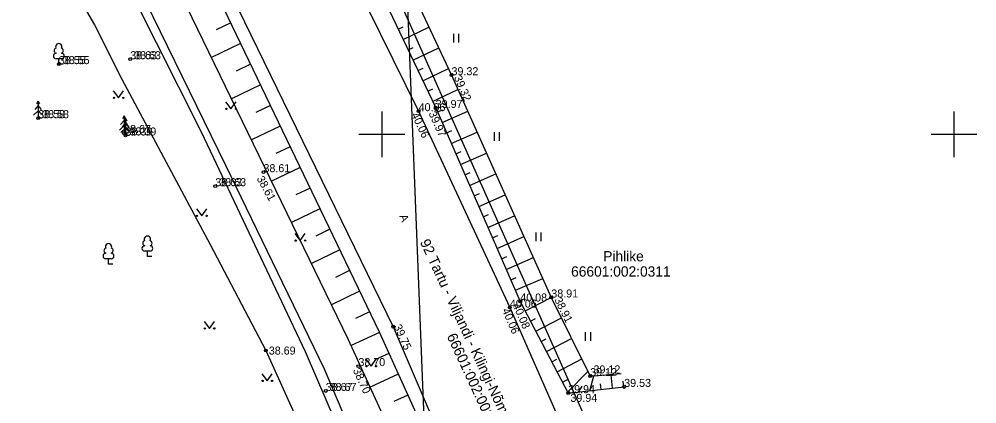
# Model space of a CAD drawing. Extents: x 627548 to 628052, y 6467984 to 6468802.
# Drawn here: x 627818.3 to 627902, y 6468376.5 to 6468410.1 of the extents above; entities that cross this region are included whole.
import ezdxf

# ---------------------------------------------------------------- set-up
doc = ezdxf.new("R2010")
doc.units = 0
for name, color, linetype in [('HALJASTUS', 7, 'Continuous'), ('KORGUS-EH2000', 7, 'Continuous'), ('MOOTKORG-EH2000', 7, 'Continuous'), ('MOOTMPUNKT', 7, 'Continuous'), ('PIIR', 7, 'Continuous'), ('PUU', 7, 'Continuous'), ('RELJEEF', 7, 'Continuous'), ('SITRASS', 7, 'Continuous'), ('TEE', 7, 'Continuous'), ('VORK', 7, 'Continuous')]:
    doc.layers.add(name, color=color, linetype=linetype)

msp = doc.modelspace()

# ---------------------------------------------------------------- linework, layer by layer
at = {"layer": 'HALJASTUS'}
for p, q in [((627856.255, 6468408.773), (627856.255, 6468408.012)), ((627856.71, 6468408.773), (627856.71, 6468408.012)), ((627826.529, 6468403.791), (627826.992, 6468403.184)), ((627826.992, 6468403.184), (627827.438, 6468403.791)), ((627836.354, 6468402.828), (627836.817, 6468402.222)), ((627836.817, 6468402.222), (627837.263, 6468402.828)), ((627859.816, 6468400.181), (627859.816, 6468399.42)), ((627860.271, 6468400.181), (627860.271, 6468399.42)), ((627833.798, 6468393.48), (627834.261, 6468392.874)), ((627834.261, 6468392.874), (627834.707, 6468393.48)), ((627842.41, 6468391.319), (627842.874, 6468390.712)), ((627842.874, 6468390.712), (627843.319, 6468391.319)), ((627863.455, 6468391.419), (627863.455, 6468390.658)), ((627863.91, 6468391.419), (627863.91, 6468390.658)), ((627834.472, 6468383.652), (627834.935, 6468383.046)), ((627834.935, 6468383.046), (627835.381, 6468383.652)), ((627867.777, 6468382.713), (627867.777, 6468381.952)), ((627868.232, 6468382.713), (627868.232, 6468381.952)), ((627848.601, 6468380.345), (627849.065, 6468379.738)), ((627849.065, 6468379.738), (627849.51, 6468380.345)), ((627839.519, 6468379.067), (627839.983, 6468378.46)), ((627839.983, 6468378.46), (627840.428, 6468379.067))]:
    msp.add_line(p, q, dxfattribs=at)
for centre in [(627826.591, 6468403.184), (627827.42, 6468403.184), (627836.416, 6468402.222), (627837.245, 6468402.222), (627833.86, 6468392.874), (627834.689, 6468392.874), (627842.473, 6468390.712), (627843.302, 6468390.712), (627834.534, 6468383.046), (627835.363, 6468383.046), (627848.664, 6468379.738), (627849.493, 6468379.738), (627839.582, 6468378.46), (627840.41, 6468378.46)]:
    msp.add_circle(centre, 0.055, dxfattribs=at)
at = {"layer": 'KORGUS-EH2000'}
for centre in [(627850.99, 6468383.197), (627839.865, 6468381.11)]:
    msp.add_circle(centre, 0.125, dxfattribs=at)
at = {"layer": 'MOOTMPUNKT'}
for centre in [(627821.775, 6468406.124), (627828.009, 6468406.553), (627856.095, 6468405.157), (627853.219, 6468402.014), (627854.711, 6468402.298), (627819.972, 6468401.404), (627827.479, 6468400.109), (627827.604, 6468399.895), (627839.659, 6468396.688), (627835.45, 6468395.464), (627862.101, 6468385.395), (627864.813, 6468385.745), (627861.194, 6468384.862), (627847.957, 6468379.753), (627868.21, 6468378.879), (627845.098, 6468377.582), (627871.184, 6468377.936), (627866.289, 6468377.389)]:
    msp.add_circle(centre, 0.125, dxfattribs=at)
at = {"layer": 'PIIR'}
for p, q in [((627893.5, 6468317.49), (627836.88, 6468444.6)), ((627826.02, 6468416.53), (627834.21, 6468400.21)), ((627834.21, 6468400.21), (627843.3, 6468381.02)), ((627843.3, 6468381.02), (627850.92, 6468363.47))]:
    msp.add_line(p, q, dxfattribs=at)
at = {"layer": 'PUU'}
for p, q in [((627822.015, 6468406.599), (627821.535, 6468406.599)), ((627821.775, 6468406.124), (627821.775, 6468406.599)), ((627822.155, 6468406.124), (627821.775, 6468406.124)), ((627819.972, 6468402.904), (627819.822, 6468402.654)), ((627820.122, 6468402.654), (627819.972, 6468402.904)), ((627819.972, 6468402.904), (627819.972, 6468401.404)), ((627819.972, 6468402.054), (627819.572, 6468401.654)), ((627819.972, 6468402.504), (627819.672, 6468402.154)), ((627820.272, 6468402.154), (627819.972, 6468402.504)), ((627820.372, 6468401.654), (627819.972, 6468402.054)), ((627820.332, 6468401.404), (627819.972, 6468401.404)), ((627827.479, 6468401.209), (627827.179, 6468400.859)), ((627827.604, 6468400.995), (627827.304, 6468400.645)), ((627827.479, 6468401.609), (627827.329, 6468401.359)), ((627827.604, 6468401.395), (627827.454, 6468401.145)), ((627827.629, 6468401.359), (627827.479, 6468401.609)), ((627827.479, 6468401.609), (627827.479, 6468400.109)), ((627827.779, 6468400.859), (627827.479, 6468401.209)), ((627827.754, 6468401.145), (627827.604, 6468401.395)), ((627827.604, 6468401.395), (627827.604, 6468399.895)), ((627827.904, 6468400.645), (627827.604, 6468400.995)), ((627827.479, 6468400.759), (627827.079, 6468400.359)), ((627827.604, 6468400.545), (627827.204, 6468400.145)), ((627827.879, 6468400.359), (627827.479, 6468400.759)), ((627828.004, 6468400.145), (627827.604, 6468400.545)), ((627827.839, 6468400.109), (627827.479, 6468400.109)), ((627827.964, 6468399.895), (627827.604, 6468399.895)), ((627829.759, 6468389.792), (627829.279, 6468389.792)), ((627829.519, 6468389.317), (627829.519, 6468389.792)), ((627829.899, 6468389.317), (627829.519, 6468389.317)), ((627826.362, 6468389.129), (627825.882, 6468389.129)), ((627826.122, 6468388.654), (627826.122, 6468389.129)), ((627826.502, 6468388.654), (627826.122, 6468388.654))]:
    msp.add_line(p, q, dxfattribs=at)
for centre, radius, start, end in [((627821.775, 6468407.644), 0.277, 332.5799, 207.4201), ((627821.538, 6468406.836), 0.238, 90.0016, 269.3953), ((627821.605, 6468407.297), 0.233, 109.02174, 253.14154), ((627821.945, 6468407.297), 0.233, 286.85082, 70.98591), ((627822.012, 6468406.836), 0.238, 270.6047, 89.9984), ((627829.519, 6468390.837), 0.277, 332.5799, 207.4201), ((627826.122, 6468390.174), 0.277, 332.5799, 207.4201), ((627829.282, 6468390.03), 0.238, 90.0016, 269.3953), ((627829.349, 6468390.49), 0.233, 109.02174, 253.14154), ((627829.689, 6468390.49), 0.233, 286.85082, 70.98591), ((627829.757, 6468390.03), 0.238, 270.6047, 89.9984), ((627825.884, 6468389.367), 0.238, 90.0016, 269.3953), ((627825.952, 6468389.827), 0.233, 109.02174, 253.14154), ((627826.292, 6468389.827), 0.233, 286.85082, 70.98591), ((627826.359, 6468389.367), 0.238, 270.6047, 89.9984)]:
    msp.add_arc(centre, radius, start, end, dxfattribs=at)
at = {"layer": 'RELJEEF'}
for p, q in [((627836.798, 6468409.725), (627835.522, 6468409.112)), ((627851.43, 6468409.171), (627851.881, 6468409.387)), ((627851.861, 6468408.269), (627854.126, 6468409.35)), ((627837.665, 6468407.923), (627835.12, 6468406.7)), ((627852.291, 6468407.366), (627852.743, 6468407.582)), ((627852.722, 6468406.464), (627854.976, 6468407.54)), ((627838.531, 6468406.12), (627837.262, 6468405.51)), ((627853.153, 6468405.561), (627853.604, 6468405.777)), ((627853.584, 6468404.659), (627855.826, 6468405.729)), ((627839.397, 6468404.317), (627836.868, 6468403.102)), ((627854.015, 6468403.757), (627854.466, 6468403.972)), ((627854.446, 6468402.854), (627856.655, 6468403.909)), ((627840.263, 6468402.515), (627839.002, 6468401.909)), ((627854.865, 6468401.946), (627855.323, 6468402.147)), ((627855.265, 6468401.03), (627857.508, 6468402.011)), ((627841.129, 6468400.712), (627838.616, 6468399.504)), ((627855.666, 6468400.114), (627856.124, 6468400.314)), ((627856.067, 6468399.198), (627858.327, 6468400.186)), ((627841.996, 6468398.909), (627840.743, 6468398.307)), ((627856.467, 6468398.281), (627856.925, 6468398.482)), ((627856.868, 6468397.365), (627859.147, 6468398.362)), ((627842.862, 6468397.106), (627840.363, 6468395.906)), ((627857.268, 6468396.449), (627857.726, 6468396.649)), ((627857.669, 6468395.533), (627859.966, 6468396.537)), ((627843.728, 6468395.304), (627842.483, 6468394.705)), ((627858.069, 6468394.616), (627858.528, 6468394.817)), ((627858.47, 6468393.7), (627860.786, 6468394.712)), ((627844.594, 6468393.501), (627842.111, 6468392.308)), ((627858.871, 6468392.784), (627859.329, 6468392.984)), ((627859.271, 6468391.868), (627861.605, 6468392.888)), ((627845.46, 6468391.698), (627844.223, 6468391.104)), ((627859.672, 6468390.951), (627860.13, 6468391.152)), ((627860.072, 6468390.035), (627862.425, 6468391.063)), ((627846.327, 6468389.896), (627843.859, 6468388.71)), ((627860.473, 6468389.119), (627860.931, 6468389.319)), ((627860.874, 6468388.202), (627863.244, 6468389.239)), ((627847.193, 6468388.093), (627845.963, 6468387.502)), ((627861.274, 6468387.286), (627861.732, 6468387.487)), ((627861.675, 6468386.37), (627864.063, 6468387.414)), ((627848.059, 6468386.29), (627845.606, 6468385.112)), ((627862.075, 6468385.454), (627862.533, 6468385.654)), ((627862.535, 6468384.566), (627864.808, 6468385.755)), ((627848.925, 6468384.488), (627847.703, 6468383.9)), ((627862.998, 6468383.68), (627863.441, 6468383.911)), ((627863.462, 6468382.794), (627865.695, 6468383.962)), ((627849.79, 6468382.684), (627847.317, 6468381.562)), ((627863.925, 6468381.907), (627864.368, 6468382.139)), ((627864.389, 6468381.021), (627866.582, 6468382.169)), ((627850.617, 6468380.863), (627849.383, 6468380.303)), ((627864.852, 6468380.135), (627865.295, 6468380.367)), ((627865.316, 6468379.249), (627867.469, 6468380.376)), ((627866.243, 6468377.477), (627868.018, 6468379.268)), ((627851.443, 6468379.042), (627848.982, 6468377.925)), ((627865.779, 6468378.363), (627866.222, 6468378.595)), ((627868.178, 6468377.6), (627868.539, 6468378.908)), ((627870.166, 6468377.822), (627870.034, 6468379)), ((627871.159, 6468377.933), (627871.104, 6468378.43)), ((627867.184, 6468377.489), (627867.498, 6468378.014)), ((627869.172, 6468377.711), (627869.116, 6468378.208)), ((627852.27, 6468377.221), (627851.043, 6468376.664))]:
    msp.add_line(p, q, dxfattribs=at)
for points in [[(627773.759, 6468549.461), (627771.296, 6468547.152), (627771.109, 6468545.291), (627781.198, 6468531.285), (627796.852, 6468507.373), (627811.934, 6468482.612), (627825.927, 6468458.237), (627843.642, 6468425.485), (627854.711, 6468402.298), (627862.101, 6468385.395), (627866.289, 6468377.389), (627871.184, 6468377.936)], [(627772.366, 6468547.143), (627782.438, 6468532.945), (627799.726, 6468507.289), (627814.065, 6468485.677), (627830.011, 6468459.01), (627845.394, 6468427.254), (627850.56, 6468416.941), (627856.095, 6468405.157), (627864.813, 6468385.745), (627868.21, 6468378.879), (627870.923, 6468379.118)], [(627798.462, 6468458.953), (627803.154, 6468462.558), (627806.385, 6468462.787), (627809.612, 6468460.426), (627831.39, 6468420.981), (627849.758, 6468382.754), (627863.845, 6468351.725), (627866.293, 6468345.533)], [(627863.023, 6468347.157), (627861.127, 6468351.404), (627847.089, 6468382.059), (627829.031, 6468419.236), (627807.647, 6468458.279), (627806.821, 6468459.718), (627803.902, 6468460.271), (627798.462, 6468458.953)]]:
    msp.add_lwpolyline(points, dxfattribs=at)
at = {"layer": 'SITRASS'}
for points in [[(627757.269, 6468529.067), (627768.1, 6468513.354), (627774.946, 6468502.943), (627783.7, 6468488.286), (627791.516, 6468476.471), (627794.222, 6468472.86), (627799.922, 6468464.28), (627804.258, 6468458.3), (627808.24, 6468452.254), (627816.937, 6468435.872), (627827.445, 6468415.491), (627836.355, 6468397.304), (627844.956, 6468379.511), (627852.286, 6468362.282), (627856.189, 6468352.574), (627857.741, 6468350.531), (627858.742, 6468350.866)], [(627858.208, 6468326.11), (627860.012, 6468334.798), (627858.052, 6468342.909), (627856.848, 6468350.174), (627857.076, 6468352.201), (627855.207, 6468358.41), (627854.195, 6468363.46), (627853.606, 6468377.354), (627852.171, 6468414.124), (627841.938, 6468447.386), (627836.234, 6468443.524)], [(627810.98, 6468412.92), (627816.008, 6468413.596), (627821.508, 6468414.106), (627822.696, 6468413.373), (627824.885, 6468409.551), (627827.286, 6468404.81), (627834.996, 6468390.373), (627839.865, 6468381.11), (627848.975, 6468360.983), (627852.832, 6468354.033), (627854.055, 6468352.951), (627855.398, 6468352.508), (627856.692, 6468352.349), (627857.78, 6468352.478), (627859.022, 6468352.51)]]:
    msp.add_lwpolyline(points, dxfattribs=at)
at = {"layer": 'TEE'}
for points in [[(627773.875, 6468550.47), (627771.331, 6468547.778), (627770.184, 6468544.969), (627779.724, 6468530.382), (627790.194, 6468514.89), (627795.603, 6468506.268), (627810.358, 6468482.16), (627820.252, 6468465.61), (627824.787, 6468457.176), (627842.022, 6468424.68), (627853.219, 6468402.014), (627861.194, 6468384.862), (627867.233, 6468371.168), (627873.073, 6468356.381), (627889.258, 6468318.908), (627892.446, 6468311.434), (627896.87, 6468301.517), (627899.405, 6468301.54), (627901.626, 6468302.361)], [(627796.263, 6468461.011), (627802.362, 6468463.279), (627805.478, 6468464.096), (627807.948, 6468463.607), (627810.898, 6468461.152), (627832.359, 6468421.429), (627850.995, 6468383.192), (627865.917, 6468348.418)]]:
    msp.add_lwpolyline(points, dxfattribs=at)
at = {"layer": 'VORK'}
for p, q in [((627850, 6468402), (627850, 6468398)), ((627900, 6468402), (627900, 6468398)), ((627848, 6468400), (627852, 6468400)), ((627898, 6468400), (627902, 6468400))]:
    msp.add_line(p, q, dxfattribs=at)

# ---------------------------------------------------------------- texts
at = {"layer": 'KORGUS-EH2000'}
for s, p in [('38.55', (627822.125, 6468406.124)), ('38.63', (627828.359, 6468406.553)), ('38.58', (627820.322, 6468401.404)), ('38.39', (627827.954, 6468399.895)), ('38.63', (627835.8, 6468395.464)), (' 38.69', (627839.865, 6468380.76)), ('39.12', (627868.502, 6468379.113)), ('38.67', (627845.448, 6468377.582)), ('39.94', (627866.484, 6468376.63))]:
    msp.add_text(s, height=0.7, dxfattribs=at).set_placement(p)
for s, rotation, p in [('39.32', 293.3149, (627856.293, 6468404.962)), ('39.97', 294.33051, (627854.07, 6468401.824)), ('40.06', 295.172, (627852.56, 6468401.712)), ('38.61', 298.8836, (627839.04, 6468396.14)), ('40.08', 293.61903, (627861.423, 6468385.075)), ('38.91', 296.5313, (627865.05, 6468385.556)), ('40.06', 293.15569, (627860.494, 6468384.639)), (' 39.75', 294.13781, (627850.933, 6468383.459)), ('38.70', 294.74244, (627847.455, 6468379.393))]:
    msp.add_text(s, height=0.7, rotation=rotation, dxfattribs=at).set_placement(p)
at = {"layer": 'MOOTKORG-EH2000'}
for s, p in [('38.55', (627821.775, 6468406.124)), ('38.63', (627828.009, 6468406.553)), ('39.32', (627856.095, 6468405.157)), ('40.06', (627853.219, 6468402.014)), ('39.97', (627854.711, 6468402.298)), ('38.58', (627819.972, 6468401.404)), ('38.67', (627827.479, 6468400.109)), ('38.39', (627827.604, 6468399.895)), ('38.61', (627839.659, 6468396.688)), ('38.63', (627835.45, 6468395.464)), ('40.08', (627862.101, 6468385.395)), ('38.91', (627864.813, 6468385.745)), ('40.06', (627861.194, 6468384.862)), ('38.70', (627847.957, 6468379.753)), ('39.12', (627868.21, 6468378.879)), ('39.53', (627871.184, 6468377.936)), ('38.67', (627845.098, 6468377.582)), ('39.94', (627866.289, 6468377.389))]:
    msp.add_text(s, height=0.7, dxfattribs=at).set_placement(p)
at = {"layer": 'PIIR'}
for s, p in [('92 Tartu - Viljandi - Kilingi-Nõmme tee', (627853.314, 6468390.593)), ('66601:002:0011', (627855.662, 6468382.367))]:
    msp.add_text(s, height=0.9, rotation=294.8815, dxfattribs=at).set_placement(p)
for s, p in [('Pihlike', (627869.35, 6468388.899)), ('66601:002:0311', (627866.543, 6468387.568))]:
    msp.add_text(s, height=0.9, dxfattribs=at).set_placement(p)
at = {"layer": 'TEE'}
msp.add_text('A', height=0.7, rotation=290.87838, dxfattribs=at).set_placement((627851.527, 6468392.849))

doc.saveas('drawing.dxf')
